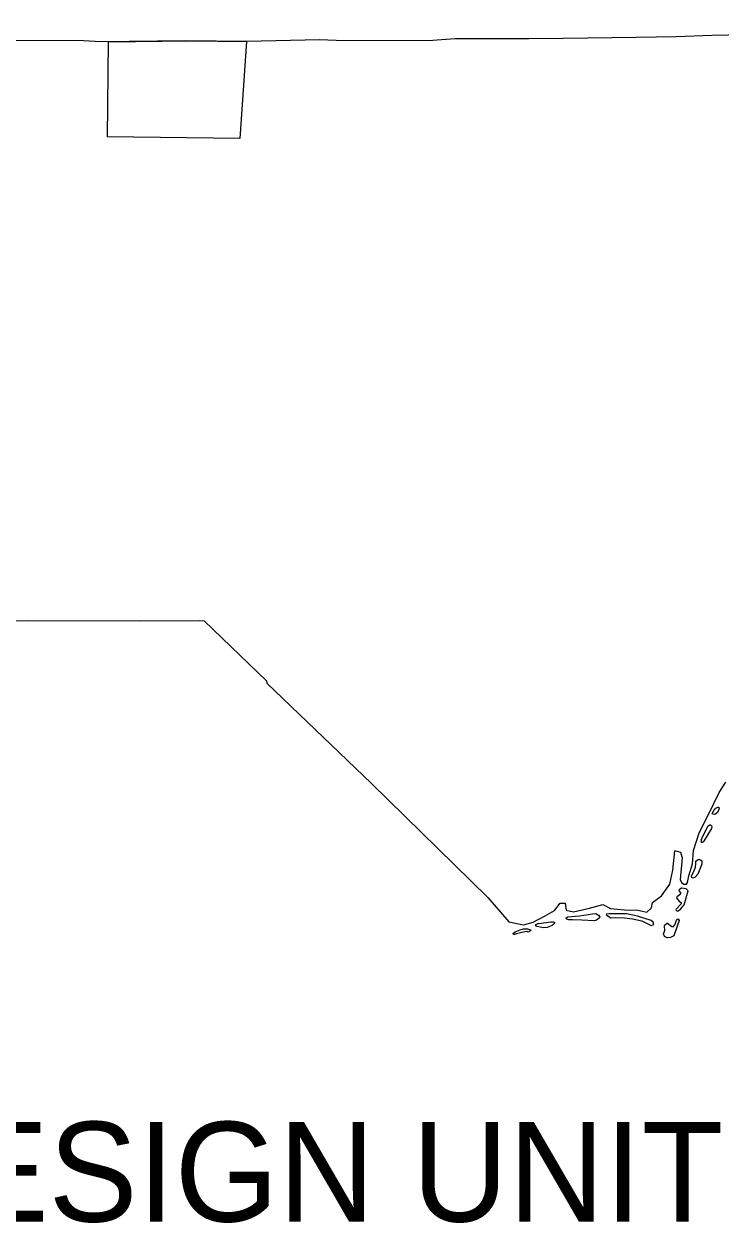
# Model space of a CAD drawing. Extents: x 2787886 to 2789612, y 1113277 to 1114394.
# Drawn here: x 2789518.76 to 2789543.9, y 1114256 to 1114299.28 of the extents above; entities that cross this region are included whole.
import ezdxf

# ---------------------------------------------------------------- set-up
doc = ezdxf.new("R2010")
doc.units = 0
doc.layers.add('Sheet_Plan_And_Profile_CELL', color=7, linetype='Continuous')

msp = doc.modelspace()

# ---------------------------------------------------------------- linework, layer by layer
at = {"layer": 'Sheet_Plan_And_Profile_CELL'}
for points in [[(2789562.224, 1114299.283), (2789559.635, 1114299.213), (2789557.432, 1114299.129), (2789555.982, 1114299.136), (2789555.564, 1114299.089), (2789551.778, 1114299.035), (2789549.483, 1114298.963), (2789547.723, 1114298.957), (2789543.571, 1114298.866), (2789542.284, 1114298.824), (2789540.845, 1114298.792), (2789538.213, 1114298.764), (2789536.974, 1114298.748), (2789534.306, 1114298.742), (2789533.511, 1114298.692), (2789530.31, 1114298.678), (2789529.431, 1114298.706), (2789526.785, 1114298.648), (2789524.604, 1114298.678), (2789521.53, 1114298.643), (2789520.905, 1114298.68), (2789517.434, 1114298.69)], [(2789562.224, 1114299.283), (2789559.635, 1114299.213), (2789557.432, 1114299.129), (2789555.982, 1114299.136), (2789555.564, 1114299.089), (2789551.778, 1114299.035), (2789549.483, 1114298.963), (2789547.723, 1114298.957), (2789543.571, 1114298.866), (2789542.284, 1114298.824), (2789540.845, 1114298.792), (2789538.213, 1114298.764), (2789536.974, 1114298.748), (2789534.306, 1114298.742), (2789533.511, 1114298.692), (2789530.31, 1114298.678), (2789529.431, 1114298.706), (2789526.785, 1114298.648), (2789524.604, 1114298.678), (2789521.53, 1114298.643), (2789520.905, 1114298.68), (2789517.434, 1114298.69)], [(2789516.808, 1114277.718), (2789518.92, 1114277.75), (2789522.942, 1114277.737), (2789525.093, 1114277.749), (2789525.256, 1114277.738), (2789527.513, 1114275.568), (2789527.527, 1114275.485), (2789531.295, 1114271.863), (2789535.494, 1114267.747), (2789536.256, 1114266.871)], [(2789516.808, 1114277.718), (2789518.92, 1114277.75), (2789522.942, 1114277.737), (2789525.093, 1114277.749), (2789525.256, 1114277.738), (2789527.513, 1114275.568), (2789527.527, 1114275.485), (2789531.295, 1114271.863), (2789535.494, 1114267.747), (2789536.256, 1114266.871)], [(2789536.256, 1114266.871), (2789536.779, 1114266.758), (2789537.135, 1114266.86), (2789537.566, 1114267.084), (2789537.899, 1114267.283), (2789538.106, 1114267.543), (2789538.282, 1114267.541), (2789538.321, 1114267.293), (2789538.583, 1114267.236), (2789539.161, 1114267.367), (2789539.646, 1114267.5), (2789539.918, 1114267.347), (2789540.426, 1114267.301), (2789540.899, 1114267.288), (2789541.226, 1114267.219), (2789541.403, 1114267.377), (2789541.437, 1114267.572), (2789541.764, 1114267.812), (2789542.055, 1114268.232), (2789542.17, 1114268.736), (2789542.239, 1114269.437), (2789542.279, 1114269.43), (2789542.448, 1114269.388), (2789542.506, 1114269.176), (2789542.437, 1114268.395), (2789542.479, 1114268.293), (2789542.568, 1114268.23), (2789542.656, 1114268.231), (2789542.695, 1114268.288), (2789542.746, 1114268.53), (2789542.877, 1114268.965), (2789542.907, 1114269.443), (2789543.115, 1114270.08), (2789543.451, 1114270.749), (2789543.837, 1114271.544), (2789544.079, 1114271.907)], [(2789536.256, 1114266.871), (2789536.779, 1114266.758), (2789537.135, 1114266.86), (2789537.566, 1114267.084), (2789537.899, 1114267.283), (2789538.106, 1114267.543), (2789538.282, 1114267.541), (2789538.321, 1114267.293), (2789538.583, 1114267.236), (2789539.161, 1114267.367), (2789539.646, 1114267.5), (2789539.918, 1114267.347), (2789540.426, 1114267.301), (2789540.899, 1114267.288), (2789541.226, 1114267.219), (2789541.403, 1114267.377), (2789541.437, 1114267.572), (2789541.764, 1114267.812), (2789542.055, 1114268.232), (2789542.17, 1114268.736), (2789542.239, 1114269.437), (2789542.279, 1114269.43), (2789542.448, 1114269.388), (2789542.506, 1114269.176), (2789542.437, 1114268.395), (2789542.479, 1114268.293), (2789542.568, 1114268.23), (2789542.656, 1114268.231), (2789542.695, 1114268.288), (2789542.746, 1114268.53), (2789542.877, 1114268.965), (2789542.907, 1114269.443), (2789543.115, 1114270.08), (2789543.451, 1114270.749), (2789543.837, 1114271.544), (2789544.079, 1114271.907)], [(2789543.589, 1114270.781), (2789543.631, 1114270.871), (2789543.683, 1114270.946), (2789543.731, 1114270.985), (2789543.79, 1114271.016), (2789543.824, 1114271.007), (2789543.837, 1114270.977), (2789543.816, 1114270.906), (2789543.778, 1114270.821), (2789543.736, 1114270.781), (2789543.681, 1114270.745), (2789543.61, 1114270.752), (2789543.592, 1114270.761), (2789543.588, 1114270.787)], [(2789543.589, 1114270.781), (2789543.631, 1114270.871), (2789543.683, 1114270.946), (2789543.731, 1114270.985), (2789543.79, 1114271.016), (2789543.824, 1114271.007), (2789543.837, 1114270.977), (2789543.816, 1114270.906), (2789543.778, 1114270.821), (2789543.736, 1114270.781), (2789543.681, 1114270.745), (2789543.61, 1114270.752), (2789543.592, 1114270.761), (2789543.588, 1114270.787)], [(2789543.194, 1114269.834), (2789543.185, 1114269.747), (2789543.2, 1114269.74), (2789543.236, 1114269.745), (2789543.286, 1114269.774), (2789543.315, 1114269.812), (2789543.572, 1114270.243), (2789543.581, 1114270.3), (2789543.571, 1114270.33), (2789543.533, 1114270.356), (2789543.496, 1114270.356), (2789543.443, 1114270.325), (2789543.41, 1114270.286), (2789543.211, 1114269.895), (2789543.194, 1114269.835)], [(2789543.194, 1114269.834), (2789543.185, 1114269.747), (2789543.2, 1114269.74), (2789543.236, 1114269.745), (2789543.286, 1114269.774), (2789543.315, 1114269.812), (2789543.572, 1114270.243), (2789543.581, 1114270.3), (2789543.571, 1114270.33), (2789543.533, 1114270.356), (2789543.496, 1114270.356), (2789543.443, 1114270.325), (2789543.41, 1114270.286), (2789543.211, 1114269.895), (2789543.194, 1114269.835)], [(2789542.985, 1114268.842), (2789542.991, 1114268.965), (2789543, 1114269.056), (2789543.043, 1114269.102), (2789543.103, 1114269.128), (2789543.161, 1114269.111), (2789543.219, 1114269.067), (2789543.218, 1114268.953), (2789543.064, 1114268.588), (2789542.977, 1114268.484), (2789542.9, 1114268.445), (2789542.851, 1114268.467), (2789542.846, 1114268.527), (2789542.907, 1114268.659), (2789542.988, 1114268.849)], [(2789542.985, 1114268.842), (2789542.991, 1114268.965), (2789543, 1114269.056), (2789543.043, 1114269.102), (2789543.103, 1114269.128), (2789543.161, 1114269.111), (2789543.219, 1114269.067), (2789543.218, 1114268.953), (2789543.064, 1114268.588), (2789542.977, 1114268.484), (2789542.9, 1114268.445), (2789542.851, 1114268.467), (2789542.846, 1114268.527), (2789542.907, 1114268.659), (2789542.988, 1114268.849)], [(2789542.45, 1114267.911), (2789542.4, 1114267.828), (2789542.318, 1114267.77), (2789542.305, 1114267.745), (2789542.311, 1114267.712), (2789542.399, 1114267.619), (2789542.446, 1114267.58), (2789542.465, 1114267.566), (2789542.464, 1114267.515), (2789542.287, 1114267.329), (2789542.272, 1114267.302), (2789542.324, 1114267.26), (2789542.36, 1114267.272), (2789542.443, 1114267.323), (2789542.578, 1114267.484), (2789542.725, 1114267.989)], [(2789542.45, 1114267.911), (2789542.4, 1114267.828), (2789542.318, 1114267.77), (2789542.305, 1114267.745), (2789542.311, 1114267.712), (2789542.399, 1114267.619), (2789542.446, 1114267.58), (2789542.465, 1114267.566), (2789542.464, 1114267.515), (2789542.287, 1114267.329), (2789542.272, 1114267.302), (2789542.324, 1114267.26), (2789542.36, 1114267.272), (2789542.443, 1114267.323), (2789542.578, 1114267.484), (2789542.725, 1114267.989)], [(2789542.725, 1114267.989), (2789542.651, 1114268.061), (2789542.477, 1114268.087), (2789542.42, 1114268.051), (2789542.38, 1114268.017), (2789542.39, 1114267.982), (2789542.45, 1114267.911)], [(2789542.725, 1114267.989), (2789542.651, 1114268.061), (2789542.477, 1114268.087), (2789542.42, 1114268.051), (2789542.38, 1114268.017), (2789542.39, 1114267.982), (2789542.45, 1114267.911)], [(2789537.337, 1114266.815), (2789537.767, 1114266.87), (2789537.853, 1114266.869), (2789537.893, 1114266.854), (2789537.879, 1114266.789), (2789537.819, 1114266.74), (2789537.636, 1114266.667), (2789537.495, 1114266.648), (2789537.273, 1114266.703), (2789537.214, 1114266.732), (2789537.251, 1114266.781), (2789537.347, 1114266.822)], [(2789537.337, 1114266.815), (2789537.767, 1114266.87), (2789537.853, 1114266.869), (2789537.893, 1114266.854), (2789537.879, 1114266.789), (2789537.819, 1114266.74), (2789537.636, 1114266.667), (2789537.495, 1114266.648), (2789537.273, 1114266.703), (2789537.214, 1114266.732), (2789537.251, 1114266.781), (2789537.347, 1114266.822)], [(2789538.384, 1114267.05), (2789538.804, 1114267.083), (2789539.27, 1114267.162), (2789539.385, 1114267.169), (2789539.482, 1114267.117), (2789539.536, 1114267.052), (2789539.523, 1114267.009), (2789539.414, 1114266.93), (2789539.331, 1114266.906), (2789538.879, 1114266.931), (2789538.554, 1114266.939), (2789538.42, 1114266.94), (2789538.347, 1114266.962), (2789538.319, 1114266.986), (2789538.319, 1114267.004), (2789538.324, 1114267.019), (2789538.382, 1114267.045)], [(2789538.384, 1114267.05), (2789538.804, 1114267.083), (2789539.27, 1114267.162), (2789539.385, 1114267.169), (2789539.482, 1114267.117), (2789539.536, 1114267.052), (2789539.523, 1114267.009), (2789539.414, 1114266.93), (2789539.331, 1114266.906), (2789538.879, 1114266.931), (2789538.554, 1114266.939), (2789538.42, 1114266.94), (2789538.347, 1114266.962), (2789538.319, 1114266.986), (2789538.319, 1114267.004), (2789538.324, 1114267.019), (2789538.382, 1114267.045)], [(2789539.765, 1114267.12), (2789539.928, 1114267.016), (2789540.099, 1114267.023), (2789540.422, 1114267.012), (2789540.715, 1114266.981), (2789541.043, 1114266.909), (2789541.287, 1114266.781), (2789541.388, 1114266.737), (2789541.478, 1114266.778), (2789541.457, 1114266.864), (2789541.386, 1114266.913), (2789540.895, 1114267.079), (2789540.501, 1114267.154), (2789539.856, 1114267.161), (2789539.765, 1114267.15), (2789539.77, 1114267.12)], [(2789539.765, 1114267.12), (2789539.928, 1114267.016), (2789540.099, 1114267.023), (2789540.422, 1114267.012), (2789540.715, 1114266.981), (2789541.043, 1114266.909), (2789541.287, 1114266.781), (2789541.388, 1114266.737), (2789541.478, 1114266.778), (2789541.457, 1114266.864), (2789541.386, 1114266.913), (2789540.895, 1114267.079), (2789540.501, 1114267.154), (2789539.856, 1114267.161), (2789539.765, 1114267.15), (2789539.77, 1114267.12)], [(2789541.972, 1114266.817), (2789542.135, 1114266.703), (2789542.175, 1114266.689), (2789542.235, 1114266.76), (2789542.313, 1114266.953), (2789542.358, 1114266.973), (2789542.394, 1114266.913), (2789542.243, 1114266.473), (2789542.209, 1114266.367), (2789542.079, 1114266.304), (2789541.968, 1114266.298), (2789541.867, 1114266.337), (2789541.835, 1114266.437), (2789541.874, 1114266.559), (2789541.862, 1114266.73), (2789541.877, 1114266.766), (2789541.962, 1114266.822), (2789541.987, 1114266.818)], [(2789541.972, 1114266.817), (2789542.135, 1114266.703), (2789542.175, 1114266.689), (2789542.235, 1114266.76), (2789542.313, 1114266.953), (2789542.358, 1114266.973), (2789542.394, 1114266.913), (2789542.243, 1114266.473), (2789542.209, 1114266.367), (2789542.079, 1114266.304), (2789541.968, 1114266.298), (2789541.867, 1114266.337), (2789541.835, 1114266.437), (2789541.874, 1114266.559), (2789541.862, 1114266.73), (2789541.877, 1114266.766), (2789541.962, 1114266.822), (2789541.987, 1114266.818)], [(2789536.397, 1114266.455), (2789536.485, 1114266.514), (2789536.662, 1114266.587), (2789536.783, 1114266.617), (2789536.859, 1114266.623), (2789536.925, 1114266.615), (2789537, 1114266.595), (2789537.034, 1114266.58), (2789537.043, 1114266.561), (2789537.037, 1114266.547), (2789536.952, 1114266.501), (2789536.931, 1114266.508), (2789536.914, 1114266.523), (2789536.834, 1114266.507), (2789536.672, 1114266.476), (2789536.534, 1114266.439), (2789536.454, 1114266.418), (2789536.423, 1114266.415), (2789536.406, 1114266.434), (2789536.397, 1114266.455)], [(2789536.397, 1114266.455), (2789536.485, 1114266.514), (2789536.662, 1114266.587), (2789536.783, 1114266.617), (2789536.859, 1114266.623), (2789536.925, 1114266.615), (2789537, 1114266.595), (2789537.034, 1114266.58), (2789537.043, 1114266.561), (2789537.037, 1114266.547), (2789536.952, 1114266.501), (2789536.931, 1114266.508), (2789536.914, 1114266.523), (2789536.834, 1114266.507), (2789536.672, 1114266.476), (2789536.534, 1114266.439), (2789536.454, 1114266.418), (2789536.423, 1114266.415), (2789536.406, 1114266.434), (2789536.397, 1114266.455)]]:
    msp.add_lwpolyline(points, dxfattribs=at)
msp.add_lwpolyline([(2789526.547, 1114295.15), (2789521.771, 1114295.207), (2789521.807, 1114298.643), (2789524.719, 1114298.676), (2789526.785, 1114298.648)], close=True, dxfattribs=at)

# ---------------------------------------------------------------- texts
msp.add_text('UTILITY DESIGN UNIT', height=3.6, rotation=0, dxfattribs=at).set_placement((2789493.704, 1114256.049))

doc.saveas('drawing.dxf')
